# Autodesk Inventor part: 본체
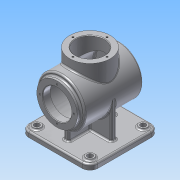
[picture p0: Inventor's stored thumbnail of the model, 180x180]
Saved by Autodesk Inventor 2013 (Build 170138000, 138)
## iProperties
Created: 2015-07
Part Number: 본체
Material: 알루미늄 6061
Document SubType Name: Modeling
Designer: ST4
Density: 2.71 g/cm^3
Mass: 1290.02 g
Surface Area: 1248.46 cm^2
Volume: 476.023 cm^3
Author: ST4
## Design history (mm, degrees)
sketch "스케치2"
  geometry: L1 (-55, 0)-(55, 0); L2 (-62, 27)-(-48, 27); L3 (-48, 27)-(-48, 37); L4 (-45, 40)-(45, 40); L5 (48, 37)-(48, 0); L6 (55, 0)-(55, 45); L7 (55, 45)-(-55, 45); L8 (-55, 45)-(-55, 38); L9 (-55, 38)-(-62, 38); L10 (-62, 38)-(-62, 27); A1 r 3 centre (-45, 37) between (-45, 40) and (-48, 37); A2 r 3 centre (45, 37) between (48, 37) and (45, 40); 2 further points
  constraints: 20 end point, 6 parallel, 4 point on circle, 4 tangent, 3 perpendicular, 2 centre point, 2 point on line, 1 coincident, 1 equal radius, 1 horizontal, 1 midpoint
  dimensions: "d0" = 110 distance of L1.start L1.end; "d2" = 90 diameter of L7 L1; "d3" = 7 distance of L8.end L9.end; "d4" = 7 distance between parallel lines of L5 L6; "d5" = 54 diameter of L2 L1; "d6" = 76 diameter of L9 L1; "d7" = 80 diameter of L4 L1; "d8" = 7 distance between parallel lines of L3 L8 (= d3); "d9" = 3 radius of A1
revolve "회전1" sketch "스케치2" stored, may be unused: angle "d10" = 90 deg
node "작업 평면1"
sketch "스케치3"
  geometry: L1 (-65, -65)-(65, -65); L2 (65, -65)-(65, 65); L3 (65, 65)-(-65, 65); L4 (-65, 65)-(-65, -65); L5 (-65, -65)-(65, 65); L6 (65, -65)-(-65, 65); 1 further point
  constraints: 12 end point, 2 midpoint, 2 parallel, 2 perpendicular, 1 horizontal
  dimensions: "d12" = 130 distance of L2.end L3.end
extrude "돌출1" join sketch "스케치3" distance "d14" = 10; taper "d15" = 0 deg
sketch "스케치4"
  geometry: L1 (65, -68)-(-65, -68) reference; L2 (-45, 0)-(-45, -68); L3 (45, 0)-(45, -68); A1 r 45 centre (0, 0) between (-45, 0) and (45, 0) reference; 1 further point
  constraints: 4 end point, 2 perpendicular, 2 point on circle, 2 point on line, 2 tangent
extrude "돌출2" join sketch "스케치4" stored distance "d16" = 10; taper "d17" = 0 deg
sketch "스케치5"
  geometry: L1 (-55, -45)-(55, -45) reference; L2 (65, -68)-(-65, -68) reference; L3 (-45, -45)-(-45, -68); 1 further point
  constraints: 2 end point, 2 point on line, 1 perpendicular
  dimensions: "d18" = 45 distance from line of L3 point (0, 0)
feature "리브1" sketch "스케치5" dims "d19" = 1, "d20" = 10, "d21" = 0, "d22" = 0, "d23" = 1, "d24" = 1
node "작업 평면2"
sketch "스케치6"
  geometry: C1 r 38 at (0, 0); 1 further point
  constraints: 1 centre point, 1 coincident
  dimensions: "d26" = 76 diameter of C1
extrude "돌출3" join sketch "스케치6" stored distance "d28" = 10; taper "d29" = 0 deg
hole "구멍1" diameter "d32" = 54; stored, may be unused: countersink angle "d36" = 90 deg, drill point angle "d38" = 0 deg; dims "d30" = 10, "d31" = 10, "d33" = 6, "d34" = 4, "d35" = 2, "d37" = 50
sketch "스케치7"
  geometry: C1 r 45 at (0, 0) reference; 1 further point
  constraints: 1 coincident, 1 other
feature "엠보싱1" sketch "스케치7" dims "d0" = 110, "d2" = 90, "d3" = 7, "d4" = 7, "d5" = 54, "d6" = 76, "d7" = 80, "d8" = 7 (= d3), "d9" = 3, "d39" = 0.5, "d40" = 0
fillet "모깎기1" dims "d41" = 15, "d42" = 3
fillet "모깎기2" dims "d43" = 3
chamfer "모따기1" distance "d44" = 1; stored, may be unused: second distance "d45" = 2, angle "d46" = 45 deg
sketch "스케치8"
  geometry: C1 r 38 at (0, 0) reference; 1 further point
  constraints: 1 vertical alignment
  dimensions: "d47" = 32 distance of point (0, 32) C1.centre
hole "구멍2" sketch "스케치8" at (0, 32) diameter "d48" = 3.242; stored, may be unused: countersink angle "d52" = 90 deg, drill point angle "d54" = 118 deg; dims "d49" = 8, "d50" = 4, "d51" = 2, "d53" = 10
sketch "스케치9"
  geometry: C1 r 38 at (0, 0) reference; 1 further point
  constraints: 1 horizontal alignment
  dimensions: "d58" = 32 distance of C1.centre point (-32, 0)
hole "구멍3" sketch "스케치9" at (-32, 0) diameter "d59" = 3.242; stored, may be unused: countersink angle "d63" = 90 deg, drill point angle "d65" = 118 deg; dims "d60" = 8, "d61" = 4, "d62" = 2, "d64" = 10
sketch "스케치10"
  geometry: C1 r 5 at (-50, 50); C2 r 7.5 at (-50, 50); A1 r 12 centre (-50, 50) between (-50, 62) and (-62, 50) reference; 1 further point
  constraints: 2 centre point, 2 coincident
  dimensions: "d69" = 10 diameter of C1; "d71" = 15 diameter of C2
extrude "돌출4" join sketch "스케치10" distance "d72" = 3; taper "d73" = 0 deg
extrude "돌출5" cut sketch "스케치10" stored distance "d74" = 3; taper "d75" = 0 deg
fillet "모깎기3" dims "d82" = 3
node "솔리드1"
mirror "대칭1"
pattern_circular "원형 패턴1" dims angle "d56" = 360 deg
pattern_circular "원형 패턴2" dims angle "d67" = 360 deg
pattern_linear "직사각형 패턴1"
other parameters: "d11" = -78
